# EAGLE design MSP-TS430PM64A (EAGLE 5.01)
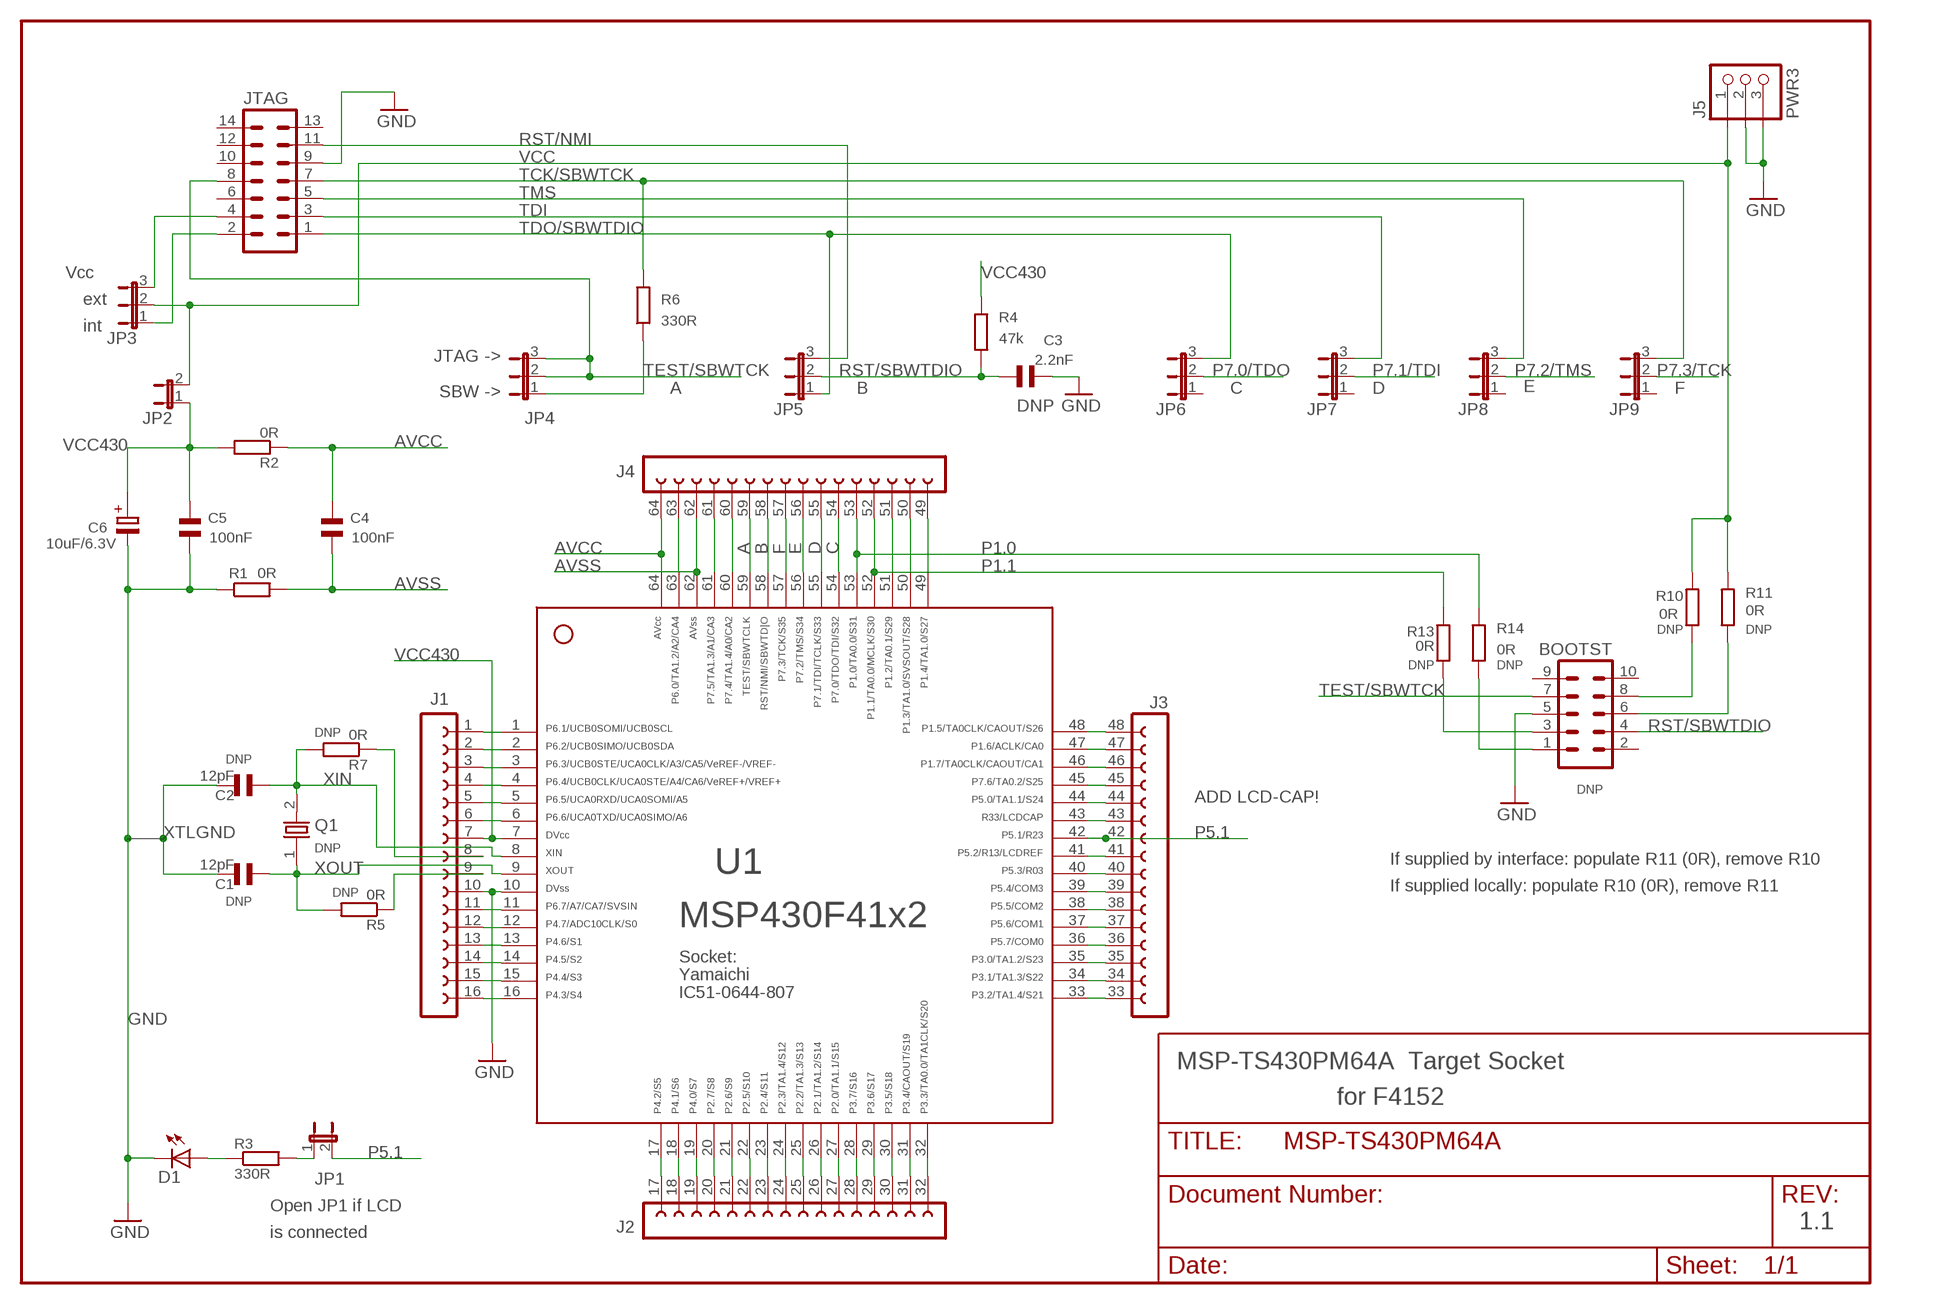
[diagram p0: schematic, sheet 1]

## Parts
BOOTST  ML10  [ML10]
C1  12pF  CSMD0805  [CSMD0805]
C2  12pF  CSMD0805  [CSMD0805]
C3  2.2nF  CSMD0805  [CSMD0805]
C4  100nF  CSMD0805  [CSMD0805]
C5  100nF  CSMD0805  [CSMD0805]
C6  10uF/6.3V  ELKO_1210  [1210ELKO]
D1  LEDCHIPLED_0805  [CHIPLED_0805]
J1  FE16-1-1  [FE16-1-1]
J2  FE16-1-2  [FE16-1-2]
J3  FE16-1-3  [FE16-1-3]
J4  FE16-1-4  [FE16-1-4]
J5  PWR3  [PWR3]
JP1  JP1E  [JP1]
JP2  JP1E  [JP1]
JP3  JP2E  [JP2]
JP4  JP2E  [JP2]
JP5  JP2E  [JP2]
JP6  JP2E  [JP2]
JP7  JP2E  [JP2]
JP8  JP2E  [JP2]
JP9  JP2E  [JP2]
JTAG  ML14  [ML14]
Q1  HCTC_XTLTCV  [TCV]
R1  0R  R_0805  [0805]
R2  0R  R_0805  [0805]
R3  330R  R_0805  [0805]
R4  47k  R_0805  [0805]
R5  0R  R_0805  [0805]
R6  330R  R_0805  [0805]
R7  0R  R_0805  [0805]
R10  0R  R_0805  [0805]
R11  0R  R_0805  [0805]
R13  0R  R_0805  [0805]
R14  0R  R_0805  [0805]
U1  F41X2---PM64QFP64-SOCKET  [IC51-0644-807]

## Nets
A: J4.59 JP4.2 JP4.3 JTAG.8 U1.59
AVCC: C4.1 J4.64 R2.1 U1.64
AVSS: C4.2 J4.62 R1.2 U1.62
B: C3.2 J4.58 JP5.2 R4.2 U1.58
C: J4.54 JP6.2 U1.54
D: J4.55 JP7.2 U1.55
E: J4.56 JP8.2 U1.56
F: J4.57 JP9.2 U1.57
GND: BOOTST.5 C3.1 C5.2 C6.- D1.C J1.10 J5.2 J5.3 JTAG.9 R1.1 U1.10
N$1: J1.9 R5.1
N$2: J1.2 U1.2
N$3: J1.1 U1.1
N$4: J1.4 U1.4
N$5: J1.5 U1.5
N$6: J1.6 U1.6
N$7: JP3.1 JTAG.2
N$8: J2.21 U1.21
N$9: J1.13 U1.13
N$10: J1.8 R7.1
N$11: J1.11 U1.11
N$12: J1.12 U1.12
N$13: J3.33 U1.33
N$14: J1.14 U1.14
N$15: J1.15 U1.15
N$16: J3.34 U1.34
N$18: J3.47 U1.47
N$19: J3.46 U1.46
N$20: J3.45 U1.45
N$21: J3.44 U1.44
N$22: J3.43 U1.43
N$23: JP3.3 JTAG.4
N$24: J3.41 U1.41
N$25: J3.40 U1.40
N$26: J3.39 U1.39
N$27: J3.38 U1.38
N$28: J3.37 U1.37
N$29: J3.36 U1.36
N$30: J3.35 U1.35
N$31: BOOTST.3 R13.1
N$32: J3.48 U1.48
N$33: JP1.1 R3.2
N$34: D1.A R3.1
N$36: J4.61 U1.61
N$37: J4.60 U1.60
N$40: J2.22 U1.22
N$41: BOOTST.1 R14.1
N$42: BOOTST.8 R10.1
N$46: J4.51 U1.51
N$47: J4.50 U1.50
N$48: J4.49 U1.49
N$49: BOOTST.6 R11.1
N$50: J2.18 U1.18
N$51: J2.19 U1.19
N$52: J2.20 U1.20
N$55: J2.23 U1.23
N$56: J2.24 U1.24
N$57: J2.25 U1.25
N$59: J2.27 U1.27
N$61: J2.29 U1.29
N$62: J2.30 U1.30
N$63: J2.31 U1.31
N$64: J2.17 U1.17
N$65: J1.16 U1.16
N$66: J2.28 U1.28
N$67: J2.32 U1.32
N$72: J4.63 U1.63
N$73: J1.3 U1.3
N$74: J2.26 U1.26
N$76: JP4.1 R6.1
P1.0: J4.53 R14.2 U1.53
P1.1: J4.52 R13.2 U1.52
P5.1: J3.42 JP1.2 U1.42
RST/NMI: JP5.3 JTAG.11
RST/SBWTDIO: BOOTST.4
TCK/SBWTCK: JP9.3 JTAG.7 R6.2
TDI: JP7.3 JTAG.3
TDO/SBWTDIO: JP5.1 JP6.3 JTAG.1
TEST/SBWTCK: BOOTST.7
TMS: JP8.3 JTAG.5
VCC: J5.1 JP2.2 JP3.2 R10.2 R11.2
VCC430: C5.1 C6.+ J1.7 JP2.1 R2.2 R4.1 U1.7
XIN: C2.1 Q1.2 R7.2 U1.8
XOUT: C1.1 Q1.1 R5.2 U1.9
XTLGND: C1.2 C2.2
Unconnected: BOOTST.2 BOOTST.9 BOOTST.10 JP6.1 JP7.1 JP8.1 JP9.1 JTAG.6 JTAG.10 JTAG.12 JTAG.13 JTAG.14

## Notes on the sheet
- Vcc
- ext
- int
- JTAG ->
- TEST/SBWTCK | RST/SBWTDIO | P7.0/TDO | P7.1/TDI | P7.2/TMS | P7.3/TCK
- SBW ->
- DNP
- DNP
- DNP
- DNP
- DNP
- DNP
- DNP
- DNP
- ADD LCD-CAP!
- DNP
- If supplied by interface: populate R11 (0R), remove R10
- DNP | If supplied locally: populate R10 (0R), remove R11
- DNP
- Socket:
- Yamaichi
- IC51-0644-807
- MSP-TS430PM64A  Target Socket
- for F4152
- Open JP1 if LCD
- 1.1
- is connected

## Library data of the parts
BOOTST = con-ml:ML10
C1-C5 = cap:CSMD0805
C6 = smd:ELKO_1210
D1 = led:LED: LED
J1 = con-lsta:FE16-1-1
J2 = con-lsta:FE16-1-2
J3 = con-lsta:FE16-1-3
J4 = con-lsta:FE16-1-4
J5 = MSP430:PWR3
JP1 JP2 = jumper:JP1E: JUMPER
JP3-JP9 = jumper:JP2E: JUMPER
JTAG = con-ml:ML14
Q1 = scrystal:HCTC_XTL
R1-R7 R10 R11 R13 R14 = smd:R_0805
U1 = TI_MSP430_v14_intern:F41X2---PM64: ***MSP430F41x2***PM64

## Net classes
0 default: width 0.254 mm, drill 0.559 mm
1 Ground: width 0.203 mm, drill 0.61 mm

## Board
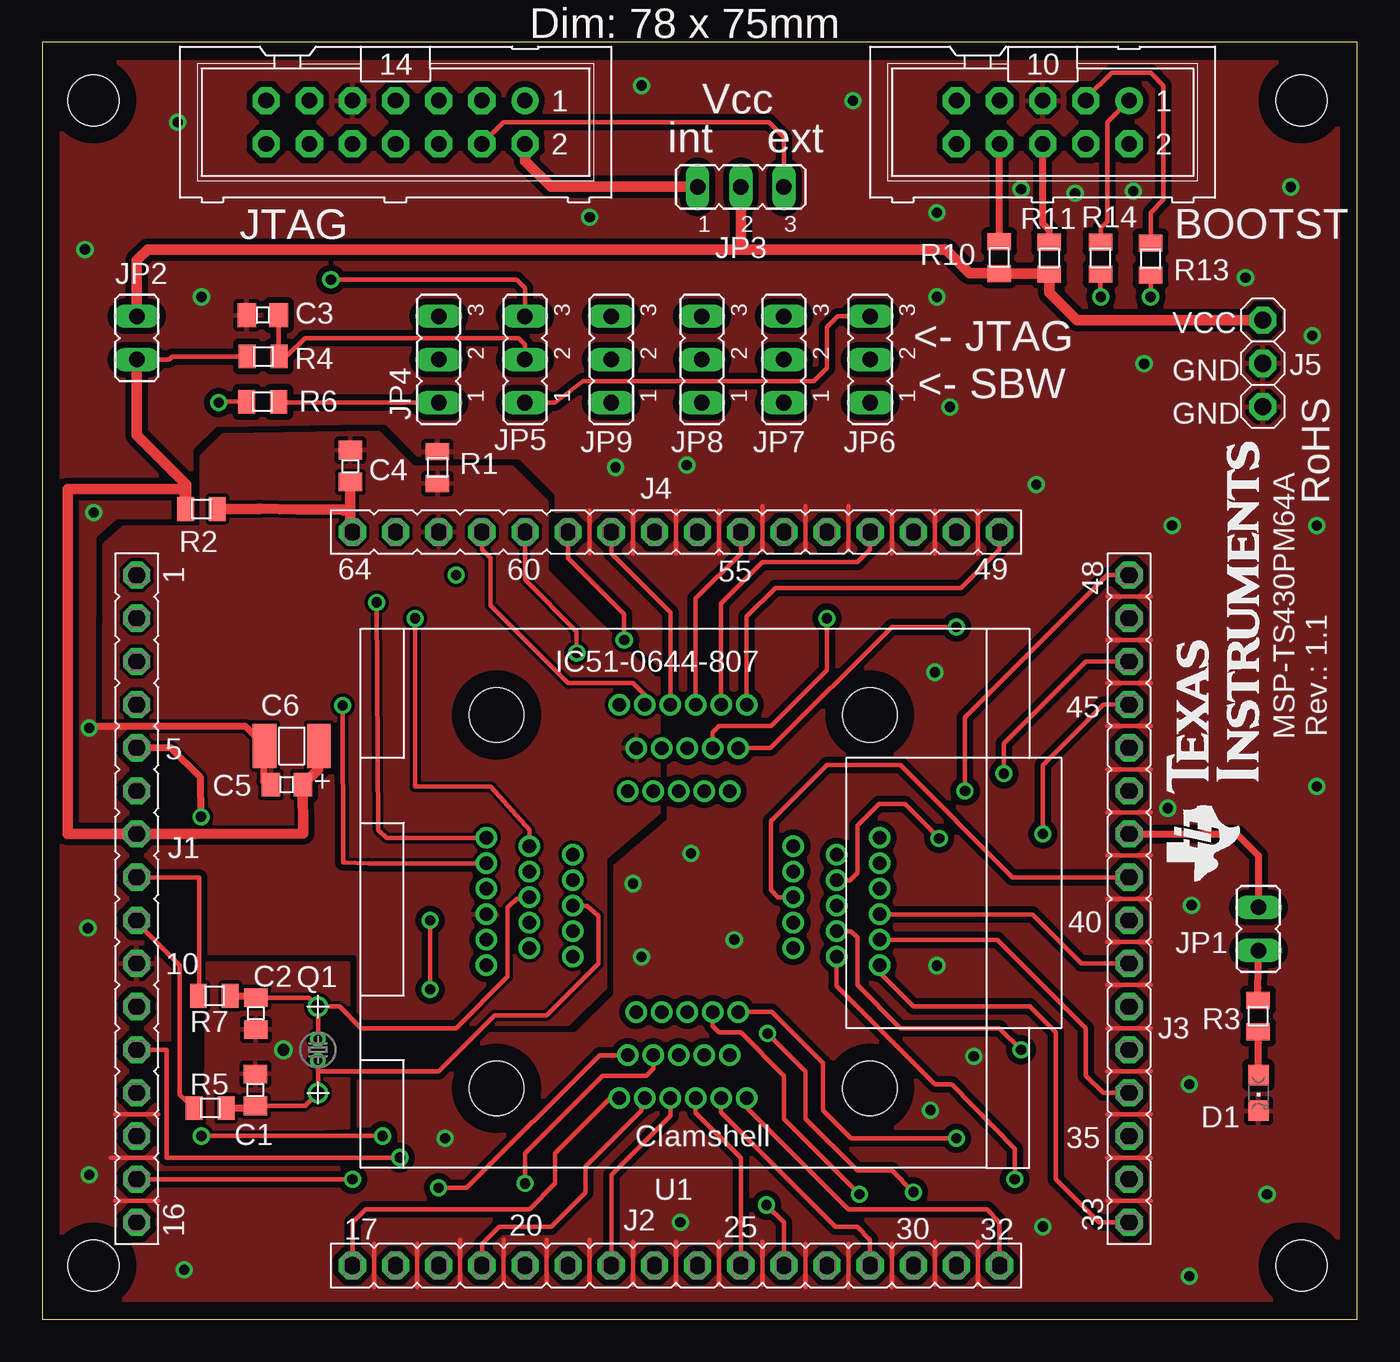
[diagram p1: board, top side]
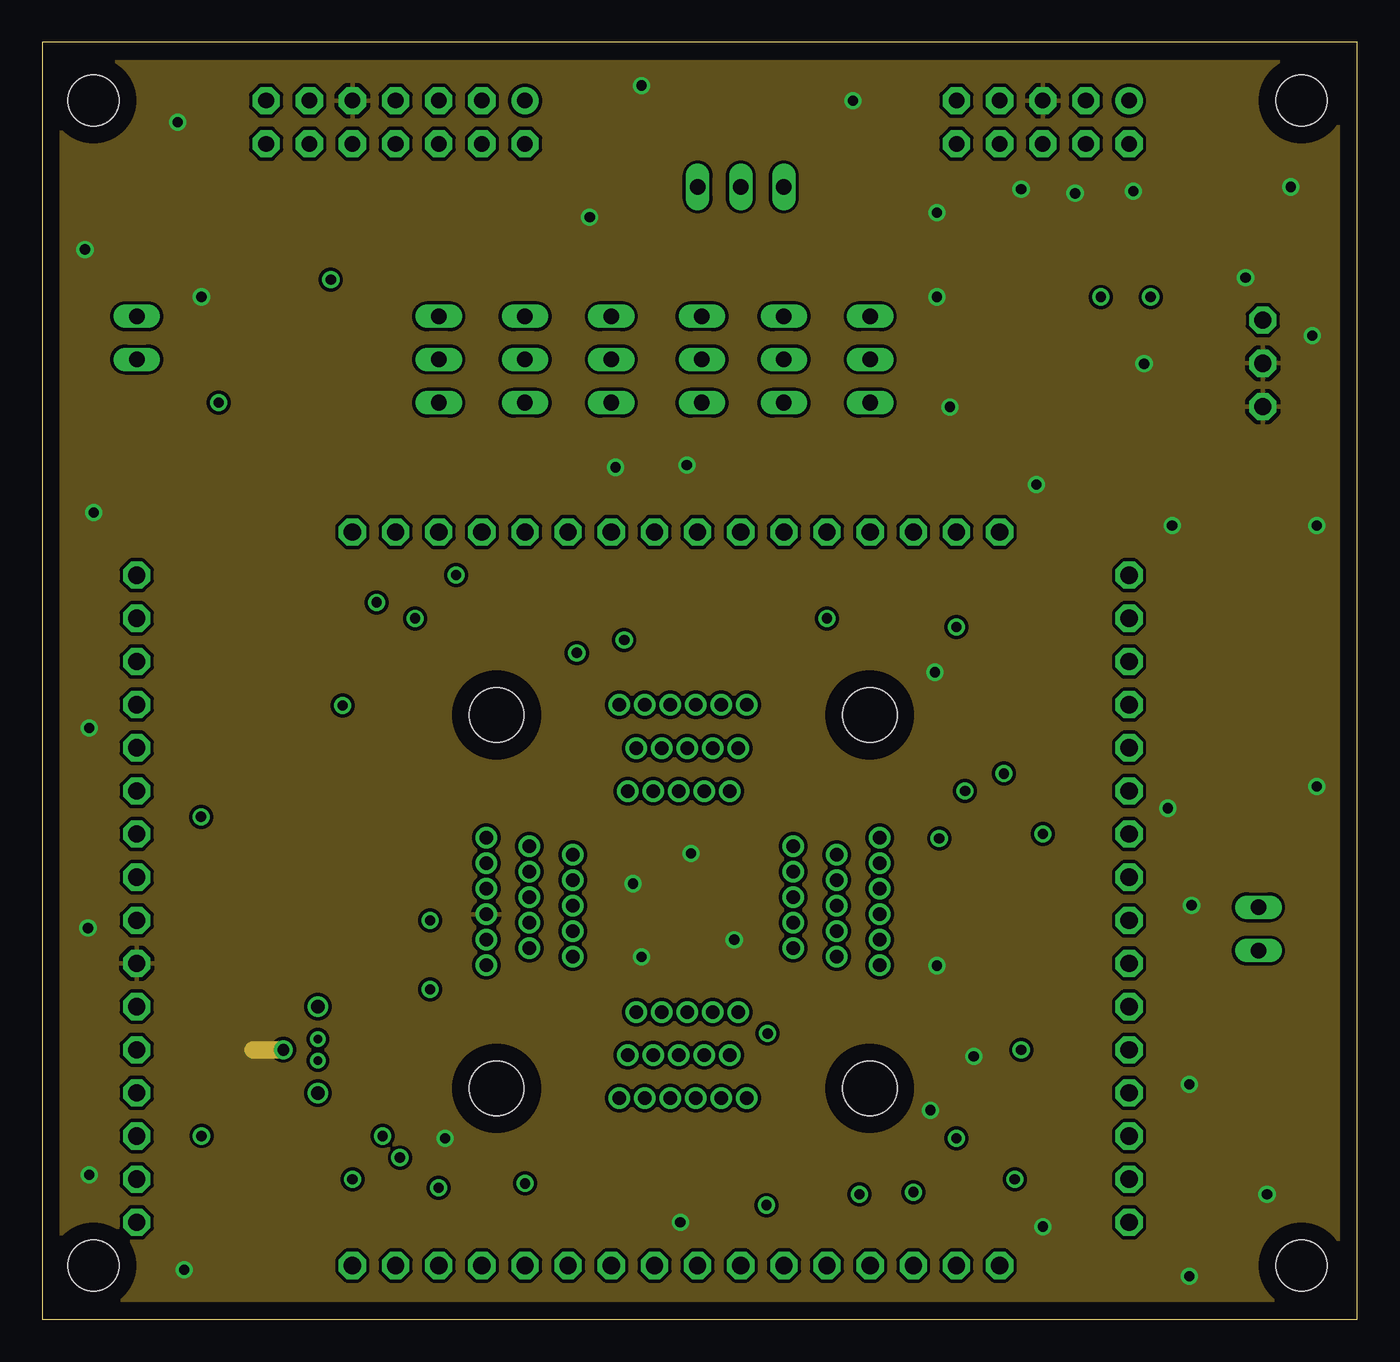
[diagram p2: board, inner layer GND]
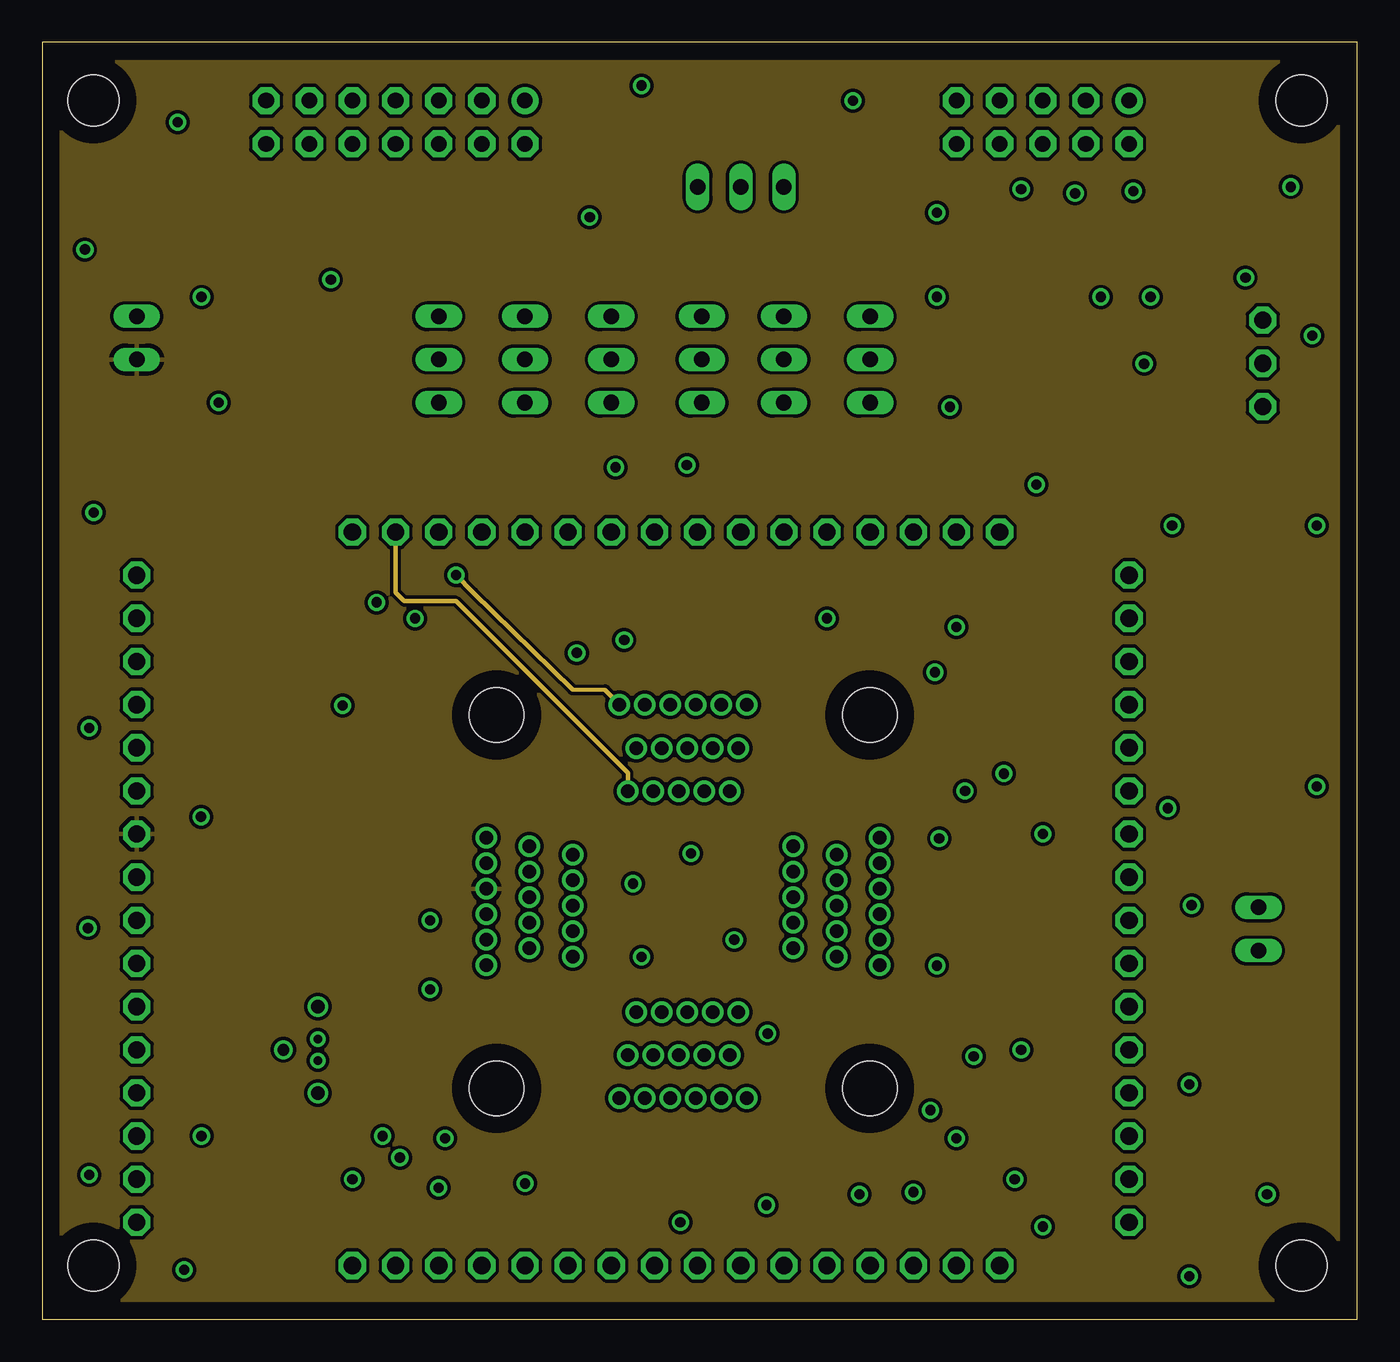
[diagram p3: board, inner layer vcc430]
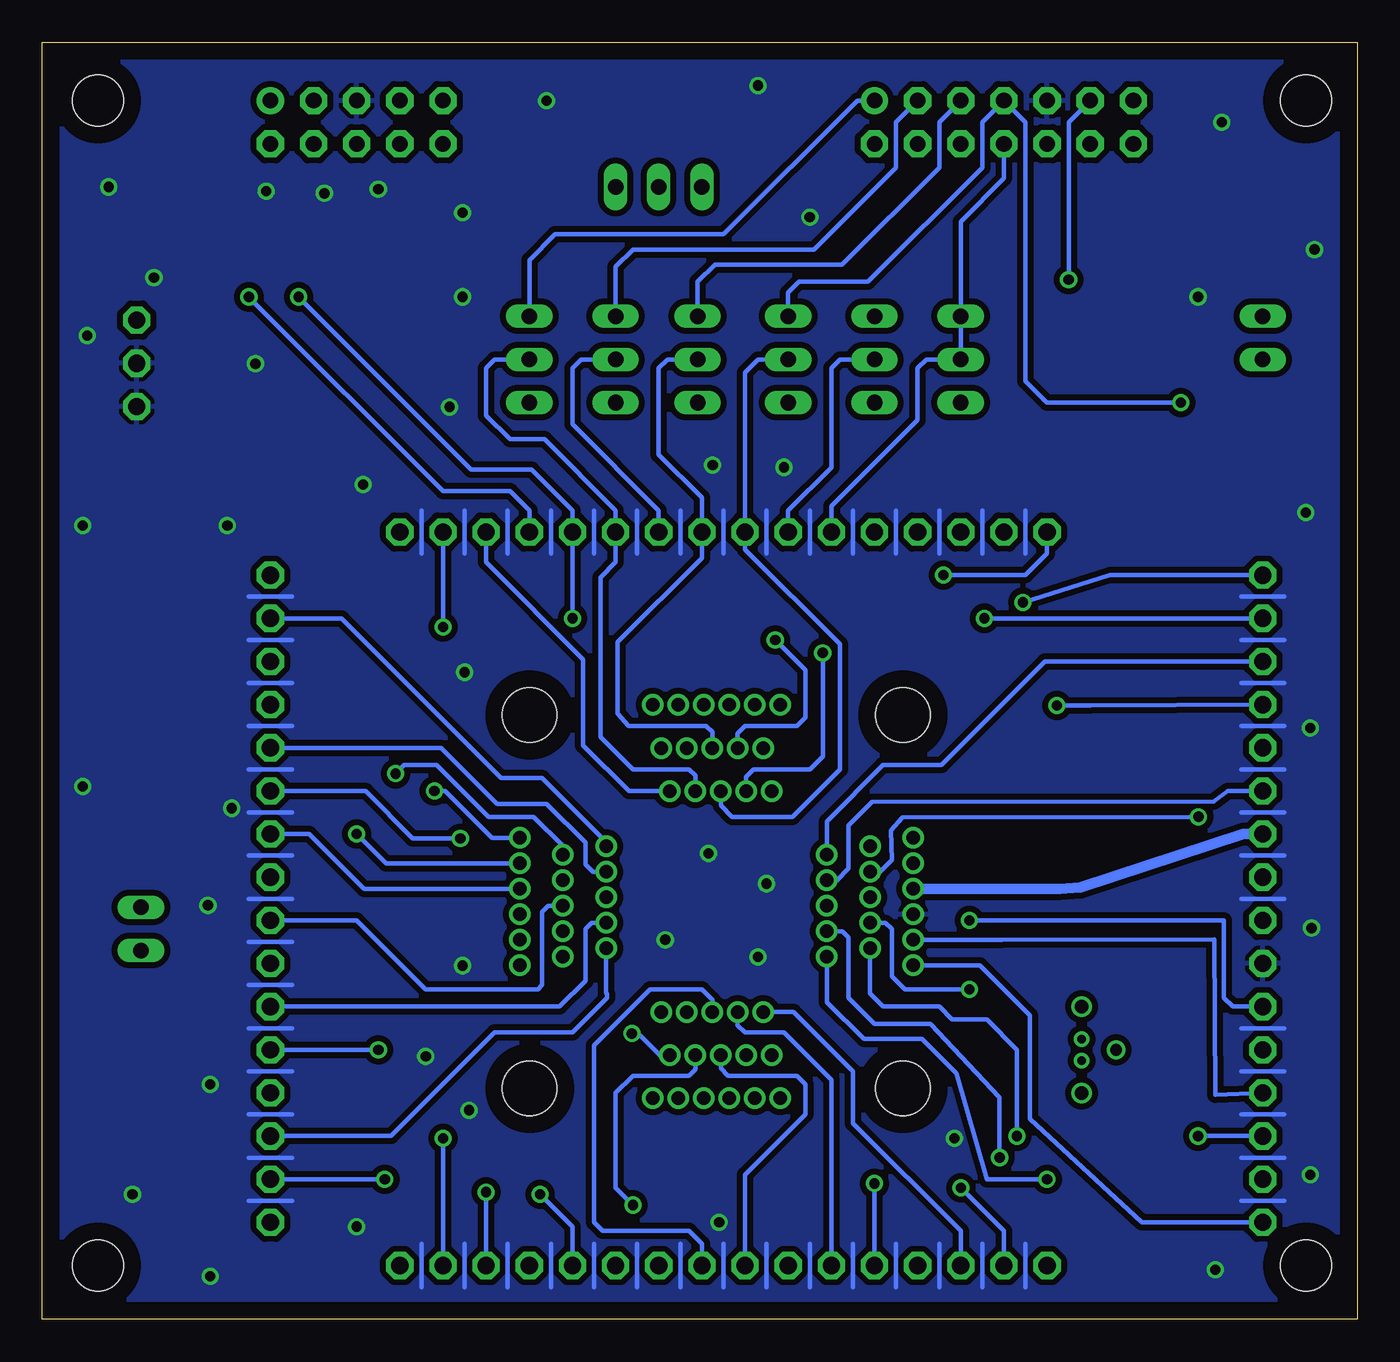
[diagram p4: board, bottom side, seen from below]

Size 77.39 x 75.17 mm. Coordinates in mm from the lower left corner, seen from the top.
Outline: 0,0 77.39,0 77.39,75.17 0,75.17 0,0
Copper layers (1*2*15*16): TOP 0.035mm / dielectric 1.5mm / GND 0.035mm / dielectric 1.5mm / vcc430 0.035mm / dielectric 1.5mm / Bottom 0.035mm
Design rules "default *": minimum track width 10mil, minimum drill 19mil, track to track 8mil, track to pad 8mil, pad to pad 8mil, via to via 8mil, smd to smd 8mil, copper to edge 40mil, drill to drill 8mil, minimum pad ring 8mil, minimum via ring 8mil, stop-mask expansion 0mil, vias tented up to drill 0mil, thermal gap 10mil
Holes 3 mm at 3.01,3.17 3.01,71.75 74.13,3.17 74.13,71.75

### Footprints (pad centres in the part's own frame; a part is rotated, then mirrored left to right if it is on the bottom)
ML10 = drill 0.914 pad 1.6 round: 1 -5.08,-1.27 | drill 0.914 pad 1.6 octagon: 2 -5.08,1.27; 3 -2.54,-1.27; 4 -2.54,1.27; 5 0,-1.27; 6 0,1.27; 7 2.54,-1.27; 8 2.54,1.27; 9 5.08,-1.27; 10 5.08,1.27
CSMD0805 = smd 1.092 x 1.397: 1 -0.94,0; 2 0.94,0
1210ELKO = smd 1.397 x 2.591: + 1.6,0; - -1.6,0
CHIPLED_0805 = smd 1.2 x 1.2: A 0,-1.05; C 0,1.05
FE16-1-1 = drill 1.016 pad 1.6 octagon: 1 -17.78,1.27; 2 -15.24,1.27; 3 -12.7,1.27; 4 -10.16,1.27; 5 -7.62,1.27; 6 -5.08,1.27; 7 -2.54,1.27; 8 0,1.27; 9 2.54,1.27; 10 5.08,1.27; 11 7.62,1.27; 12 10.16,1.27; 13 12.7,1.27; 14 15.24,1.27; 15 17.78,1.27; 16 20.32,1.27
FE16-1-2 = drill 1.016 pad 1.6 octagon: 17 -17.78,1.27; 18 -15.24,1.27; 19 -12.7,1.27; 20 -10.16,1.27; 21 -7.62,1.27; 22 -5.08,1.27; 23 -2.54,1.27; 24 0,1.27; 25 2.54,1.27; 26 5.08,1.27; 27 7.62,1.27; 28 10.16,1.27; 29 12.7,1.27; 30 15.24,1.27; 31 17.78,1.27; 32 20.32,1.27
FE16-1-3 = drill 1.016 pad 1.6 octagon: 33 -17.78,1.27; 34 -15.24,1.27; 35 -12.7,1.27; 36 -10.16,1.27; 37 -7.62,1.27; 38 -5.08,1.27; 39 -2.54,1.27; 40 0,1.27; 41 2.54,1.27; 42 5.08,1.27; 43 7.62,1.27; 44 10.16,1.27; 45 12.7,1.27; 46 15.24,1.27; 47 17.78,1.27; 48 20.32,1.27
FE16-1-4 = drill 1.016 pad 1.6 octagon: 49 -17.78,1.27; 50 -15.24,1.27; 51 -12.7,1.27; 52 -10.16,1.27; 53 -7.62,1.27; 54 -5.08,1.27; 55 -2.54,1.27; 56 0,1.27; 57 2.54,1.27; 58 5.08,1.27; 59 7.62,1.27; 60 10.16,1.27; 61 12.7,1.27; 62 15.24,1.27; 63 17.78,1.27; 64 20.32,1.27
PWR3 = drill 1.016 pad 1.6 octagon: 1 -2.54,0; 2 0,0; 3 2.54,0
JP1 = drill 0.914 long: 1 0,-1.27; 2 0,1.27
JP2 = drill 0.914 long: 1 -2.54,0; 2 0,0; 3 2.54,0
ML14 = drill 0.914 pad 1.6 round: 1 -7.62,-1.27 | drill 0.914 pad 1.6 octagon: 2 -7.62,1.27; 3 -5.08,-1.27; 4 -5.08,1.27; 5 -2.54,-1.27; 6 -2.54,1.27; 7 0,-1.27; 8 0,1.27; 9 2.54,-1.27; 10 2.54,1.27; 11 5.08,-1.27; 12 5.08,1.27; 13 7.62,-1.27; 14 7.62,1.27
TCV = drill 0.5 round: 1 -0.635,0; 2 0.635,0
0805 = smd 1 x 1.4: 1 -0.94,0; 2 0.94,0
IC51-0644-807 = drill 0.8 pad 1.27 round: 1 11.652,-4.194; 2 9.112,-3.694; 3 6.572,-3.194; 4 11.652,-2.694; 5 9.112,-2.194; 6 6.572,-1.694; 7 11.652,-1.194; 8 9.112,-0.694; 9 6.572,-0.194; 10 11.652,0.306; 11 9.112,0.806; 12 6.572,1.306; 13 11.652,1.806; 14 9.112,2.306; 15 6.572,2.806; 16 11.652,3.306; 17 3.822,11.136; 18 3.322,8.596; 19 2.822,6.056; 20 2.322,11.136; 21 1.822,8.596; 22 1.322,6.056; 23 0.822,11.136; 24 0.322,8.596; 25 -0.178,6.056; 26 -0.678,11.136; 27 -1.178,8.596; 28 -1.678,6.056; 29 -2.178,11.136; 30 -2.678,8.596; 31 -3.178,6.056; 32 -3.678,11.136; 33 -11.508,3.306; 34 -8.968,2.806; 35 -6.428,2.306; 36 -11.508,1.806; 37 -8.968,1.306; 38 -6.428,0.806; 39 -11.508,0.306; 40 -8.968,-0.194; 41 -6.428,-0.694; 42 -11.508,-1.194; 43 -8.968,-1.694; 44 -6.428,-2.194; 45 -11.508,-2.694; 46 -8.968,-3.194; 47 -6.428,-3.694; 48 -11.508,-4.194; 49 -3.678,-12.024; 50 -3.178,-9.484; 51 -2.678,-6.944; 52 -2.178,-12.024; 53 -1.678,-9.484; 54 -1.178,-6.944; 55 -0.678,-12.024; 56 -0.178,-9.484; 57 0.322,-6.944; 58 0.822,-12.024; 59 1.322,-9.484; 60 1.822,-6.944; 61 2.322,-12.024; 62 2.822,-9.484; 63 3.322,-6.944; 64 3.822,-12.024 | hole 3.2: -10.922,10.541; 11.049,10.541; 11.049,-11.43; -10.922,-11.43

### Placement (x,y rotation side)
BOOTST  58.89,70.48 180 top
C1  12.54,13.51 90 top
C2  12.56,18 270 top
C3  12.97,59.13 0 top
C4  18.12,50.24 90 top
C5  14.39,31.48 180 top
C6  14.68,33.76 0 top
D1  71.59,13.33 180 top
J1  4.28,26.03 270 top
J2  36.03,1.9 0 top
J3  65.24,23.49 90 top
J4  38.57,47.62 180 top
J5  71.84,56.28 270 top
JP1  71.59,22.98 0 top
JP2  5.55,57.78 0 top
JP3  41.11,66.67 0 top
JP4  23.33,56.51 90 top
JP5  28.41,56.51 90 top
JP6  48.73,56.51 90 top
JP7  43.65,56.51 90 top
JP8  38.82,56.51 90 top
JP9  33.49,56.51 90 top
JTAG  20.79,70.48 180 top
Q1  16.22,15.87 90 top
R1  23.25,50.13 270 top
R2  9.36,47.71 180 top
R3  71.56,17.85 90 top
R4  12.99,56.69 0 top
R5  9.87,12.44 0 top
R6  12.97,54.02 180 top
R7  10.12,19.05 0 top
R10  56.32,62.5 270 top
R11  59.27,62.48 270 top
R13  65.24,62.43 270 top
R14  62.29,62.48 270 top
U1  37.78,24.15 180 top
U$1  [LOGO2008_TPLACE]  69.3,35.81 90 top

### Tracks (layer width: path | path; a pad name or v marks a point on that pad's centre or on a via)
A  (via drill 0.6)
  TOP 0.254: v34.25,40 34.25,41.52 30.95,44.83 J4.59
  Bottom 0.254: U1.59 36.46,34.49 36.03,34.92 32.98,34.92 32.47,35.43 32.47,38.22 v34.25,40 | J4.59 30.95,47.87 25.87,52.95 25.87,56 25.36,56.51 JP4.2 JP4.3 23.33,64.64 20.79,67.18 JTAG.8
AVCC  (via drill 0.6)
  TOP 0.61: J4.64 18.25,46.6 18.12,46.73 18.12,47.62 | 18.12,47.62 C4.1 | 18.12,47.62 18,47.62 17.95,47.67 17.79,47.67 17.74,47.62 17.69,47.67 15.02,47.67 12.79,47.75 12.75,47.71 R2.1
  vcc430 0.254: U1.64 33.12,37.06 31.2,37.08 25.36,42.79 v24.35,43.81
  Bottom 0.254: v24.35,43.81 19.52,43.81 18.25,45.08 J4.64
AVSS
  pour TOP (rank 2): 27.65,50.16 29.68,48.13 29.68,44.06 36.03,37.71 36.28,37.71 36.28,29.84 33.11,27.17 33.11,19.55 30.95,17.39 19.09,17.37 19.09,21.53 9.31,21.53 9.31,17.14 4.33,17.14 3.57,17.9 3.67,45.61 4.79,46.6 9.39,46.6 9.39,50.79 10.66,52.06 19.77,52.19 21.81,50.16
B
  TOP 0.254: U1.58 36.96,41.61 33.49,45.08 J4.58 | JP5.2 28.41,57.4 28.03,57.78 15.46,57.78 14.44,56.76 14.06,56.76 13.98,56.69 R4.2 13.93,56.76 13.91,56.79 C3.2
  Bottom 0.254: JP5.2 30.44,56.51 30.95,56 30.95,50.16 33.49,47.62 J4.58
C
  Bottom 0.254: U1.54 38.96,32.01 39.33,32.38 42.63,32.38 44.54,34.28 44.54,43.68 43.65,44.57 J4.54 43.65,47.62 47.84,51.81 49.87,51.81 51.27,53.21 51.27,56 50.76,56.51 JP6.2
D
  TOP 0.254: U1.55 38.46,42.43 41.11,45.08 J4.55
  Bottom 0.254: JP7.2 45.68,56.51 46.19,56 46.19,52.7 41.11,47.62 J4.55
E
  Bottom 0.254: U1.56 37.96,34.56 38.32,34.92 42.89,34.92 43.52,35.68 43.52,39.87 38.57,44.83 J4.56 38.57,48.38 41.11,50.92 41.11,56 40.6,56.51 JP8.2
F
  Bottom 0.254: U1.57 37.46,30.25 36.79,29.59 33.24,29.59 30.44,32.38 30.44,39.75 36.03,45.33 J4.57 36.03,55.75 35.27,56.51 JP9.2
GND  (via drill 0.6)
  TOP 0.254: 4.03,9.52 6.57,9.52 | 4.28,12.06 6.82,12.06 | 4.28,6.98 6.82,6.98 | 19.52,1.9 19.52,4.44 | 22.06,1.9 22.06,4.44 | 24.6,2.15 24.6,4.69 | 27.14,2.15 27.14,4.69 | 29.68,2.15 29.68,4.69 | 32.22,2.15 32.22,4.69 | 34.76,2.03 34.76,4.57 | 37.3,2.03 37.3,4.57 | 39.84,2.03 39.84,4.57 | 42.38,2.03 42.38,4.57 | 44.92,1.9 44.92,4.44 | 47.46,1.9 47.46,4.44 | 50,1.9 50,4.44 | 52.54,2.03 52.54,4.57 | 55.08,2.03 55.08,4.57 | 62.7,6.98 65.24,6.98 | 62.7,9.52 65.24,9.52 | 62.7,12.06 65.24,12.06 | 62.7,14.6 65.24,14.6 | 62.7,17.14 65.24,17.14 | 62.7,19.68 65.24,19.68 | 62.7,22.22 65.24,22.22 | 62.7,24.76 65.24,24.76 | 62.7,27.3 65.24,27.3 | 62.7,29.84 65.24,29.84 | 62.7,32.38 65.24,32.38 | 62.7,34.92 65.24,34.92 | 62.7,37.46 65.24,37.46 | 62.7,40 65.24,40 | 62.7,42.54 65.24,42.54 | 55.08,45.08 55.08,47.62 | 52.54,45.08 52.54,47.62 | 50,45.08 50,47.62 | 47.46,45.33 47.46,47.87 | 44.92,45.33 44.92,47.87 | 42.38,45.33 42.38,47.87 | 39.84,45.08 39.84,47.62 | 37.3,45.08 37.3,47.62 | 34.76,45.08 34.76,47.62 | 32.22,45.08 32.22,47.62
  TOP 0.406: C5.2 13.02,31.68 13.02,33.78 13.07,33.78 C6.- 11.92,34.92 3.11,34.92 v2.76,34.82
  GND 1.016: 12.41,15.87 14.19,15.87
  Bottom 0.254: 4.28,37.46 6.82,37.46 | 4.28,40 6.82,40 | 4.28,42.54 6.82,42.54 | 4.28,34.92 6.82,34.92 | 4.28,32.38 6.82,32.38 | 4.28,29.84 6.82,29.84 | 4.28,27.3 6.82,27.3 | 4.28,24.76 6.82,24.76 | 4.28,17.14 6.82,17.14 | 4.28,14.6 6.82,14.6 | 4.28,12.06 6.82,12.06 | 4.28,9.52 6.82,9.52 | 4.28,6.98 6.82,6.98 | 19.52,1.9 19.52,4.44 | 22.06,1.9 22.06,4.44 | 24.6,1.9 24.6,4.44 | 27.14,1.9 27.14,4.44 | 29.68,1.9 29.68,4.44 | 32.22,1.9 32.22,4.44 | 34.76,1.9 34.76,4.44 | 37.3,1.9 37.3,4.44 | 39.84,1.9 39.84,4.44 | 42.38,1.9 42.38,4.44 | 44.92,1.9 44.92,4.44 | 47.46,1.9 47.46,4.44 | 50,1.9 50,4.44 | 52.54,1.9 52.54,4.44 | 55.08,1.9 55.08,4.44 | 62.7,6.98 65.24,6.98 | 62.7,9.52 65.24,9.52 | 62.7,12.06 65.24,12.06 | 62.7,14.6 65.24,14.6 | 62.7,17.14 65.24,17.14 | 62.7,19.68 65.24,19.68 | 62.7,22.22 65.24,22.22 | 62.7,24.76 65.24,24.76 | 62.7,27.3 65.24,27.3 | 62.7,29.84 65.24,29.84 | 62.7,32.38 65.24,32.38 | 62.7,34.92 65.24,34.92 | 62.7,37.46 65.24,37.46 | 62.7,40 65.24,40 | 62.7,42.54 65.24,42.54 | 55.08,45.08 55.08,47.62 | 52.54,45.08 52.54,47.62 | 50,45.08 50,47.62 | 47.46,45.08 47.46,47.62 | 42.38,45.08 42.38,47.62 | 39.84,45.08 39.84,47.62 | 37.3,45.08 37.3,47.62 | 34.76,45.08 34.76,47.62 | 32.22,45.08 32.22,47.62 | 29.68,45.08 29.68,47.62 | 27.14,45.08 27.14,47.62 | 24.6,45.08 24.6,47.62 | 22.06,45.08 22.06,47.62 | 19.52,45.08 19.52,47.62 | 44.92,45.08 44.92,47.62
  other vias: 38.19,27.43 34.76,25.65 35.27,21.33 40.73,22.35 60.79,66.29 57.62,66.54 64.22,66.42 73.5,66.67 70.83,61.34 74.77,57.91 75.02,46.73 75.02,31.36 66.26,30.09 67.65,24.38 67.53,13.84 72.1,7.36 67.53,2.54 58.89,5.46 54.83,15.49 52.67,20.82 52.29,12.31 37.55,5.71 23.71,10.66 8.34,2.92 2.76,8.5 2.68,23.03 3.01,47.49 2.5,62.99 7.96,70.48 9.36,60.19 52.67,60.19 53.43,53.72 35.27,72.64 47.71,71.75 52.67,65.15 64.86,56.26 58.51,49.14 52.54,38.09 66.51,46.73 37.93,50.29 33.74,50.16 32.22,64.89
  pour TOP (isolate 0.356, rank 3): 0.41,0.38 76.89,0.38 76.92,49.14 76.92,74.48 0.41,74.48
  pour Bottom (isolate 0.356): 0.47,0.38 76.91,0.35 76.91,74.58 3.64,74.48 0.47,74.48
  pour GND (rank 2): 0.47,0.63 76.67,0.63 76.67,74.29 0.47,74.29
N$1
  TOP 0.254: R5.1 8.09,13.2 8.09,20.82 5.55,23.36 J1.9
N$2  (via drill 0.6)
  TOP 0.254: U1.2 28.67,28.82 26.38,31.36 21.93,31.36 v21.93,41.27
  Bottom 0.254: J1.2 v21.93,41.27
N$3  (via drill 0.6)
  TOP 0.254: U1.1 20.25,28.34 19.77,28.82 v19.67,42.21
  Bottom 0.254: v19.67,42.21 14.57,43.81 J1.1
N$4  (via drill 0.6)
  TOP 0.254: U1.4 19.21,26.84 17.69,26.89 v17.67,36.14
  Bottom 0.254: v17.67,36.14 15.71,36.14 J1.4
N$5  (via drill 0.6)
  TOP 0.406: J1.5 7.56,33.65 9.31,31.9 v9.34,29.59
  Bottom 0.254: U1.5 28.1,26.34 27.39,27.05 27.45,28.77 26.76,29.54 v9.34,29.59
N$6
  Bottom 0.254: U1.6 30.63,25.84 29.93,26.54 29.93,29.08 28.56,30.45 8.45,30.47 7.61,31.11 J1.6
N$7
  TOP 0.61: JTAG.2 28.41,68.19 29.93,66.67 JP3.1
N$8  (via drill 0.6)
  TOP 0.254: U1.21 35.96,14.79 35.52,14.35 32.98,14.35 28.66,10.03 28.41,9.77 v28.41,8
  Bottom 0.254: J2.21 v28.41,8
N$9
  Bottom 0.254: U1.13 20.91,22.34 8.39,22.37 8.34,13.2 J1.13
N$10
  TOP 0.254: 9.23,19.05 9.23,26.03 J1.8
  TOP 0.406: R7.1 9.23,19.05
N$11  (via drill 0.6)
  TOP 0.254: v22.82,23.49 v22.82,19.43
  Bottom 0.254: U1.11 27.76,23.34 27.39,22.98 27.39,20.19 26.63,19.43 v22.82,19.43 | v22.82,23.49 7.84,23.49 7.84,18.92 7.33,18.41 J1.11
N$12  (via drill 0.6)
  TOP 0.254: J1.12 7.33,15.87 7.33,9.52 v21.04,9.52
  Bottom 0.254: U1.12 30.3,22.84 29.93,22.47 29.93,18.92 28.41,17.39 25.11,17.39 21.04,13.08 v21.04,9.52
N$13
  TOP 0.254: U1.33 49.29,20.39 51.27,18.41 58.13,18.41 59.65,16.89 59.65,8.25 62.19,5.71 J3.33
N$14  (via drill 0.6)
  TOP 0.254: v9.36,10.79 v20.03,10.79
  Bottom 0.254: U1.14 28.67,19.18 27.9,18.41 24.6,18.41 23.84,17.65 21.81,17.65 20.03,15.87 v20.03,10.79 | J1.14 v9.36,10.79
N$15  (via drill 0.6)
  TOP 0.254: J1.15 v18.25,8.25
  Bottom 0.254: U1.15 31.21,18.67 29.05,16.5 25.62,16.5 23.58,14.47 21.81,8.25 v18.25,8.25
N$16  (via drill 0.6)
  TOP 0.254: U1.34 46.75,19.63 52.54,13.84 53.56,13.84 57.24,10.03 v57.24,8.25
  Bottom 0.254: v57.24,8.25 J3.34
N$18
  Bottom 0.254: U1.47 44.21,28.11 47.97,31.87 50.38,31.87 59.78,41.27 J3.47
N$19  (via drill 0.6)
  TOP 0.254: v56.6,32.13 56.6,33.9 61.43,38.73 J3.46
  Bottom 0.254: U1.46 46.75,27.86 48.48,29.59 51.14,29.59 54.19,32.63 56.1,32.63 v56.6,32.13
N$20  (via drill 0.6)
  TOP 0.254: v58.89,28.57 58.89,32.63 62.45,36.19 J3.45
  Bottom 0.254: U1.45 57.16,26.84 v58.89,28.57
N$21
  Bottom 0.254: U1.44 44.98,26.34 45.43,26.79 45.43,28.06 47.71,30.35 50.63,30.35 53.94,33.65 J3.44
N$22  (via drill 0.6)
  TOP 0.254: U1.43 47.53,25.84 47.97,26.28 47.97,29.08 49.24,30.35 50.76,30.35 v52.79,28.32
  Bottom 0.254: v52.79,28.32 55.59,28.32 58.38,31.11 J3.43
N$23
  TOP 0.254: JP3.3 43.65,69.59 42.76,70.48 27.14,70.48 JTAG.4
N$24
  TOP 0.254: U1.41 43.31,24.84 42.89,25.27 42.89,29.33 46.19,32.63 50.51,32.63 57.11,26.03 J3.41
N$25
  Bottom 0.254: U1.40 47.62,24.34 47.97,24 47.97,19.68 48.22,19.43 54.83,19.43 58.89,23.49 J3.40
N$26
  TOP 0.254: U1.39 58.28,23.84 61.18,20.95 J3.39
N$27
  Bottom 0.254: U1.38 45.07,23.34 45.43,22.98 45.43,19.93 46.95,18.41 J3.38
N$28  (via drill 0.6)
  TOP 0.254: U1.37 47.6,22.84 47.97,22.47 47.97,19.68 50.51,17.14 56.35,17.14 v57.62,15.87
  Bottom 0.254: v57.62,15.87 J3.37
N$29
  TOP 0.254: U1.36 56.23,22.34 61.43,17.14 61.43,14.35 62.45,13.33 J3.36
N$30
  Bottom 0.254: U1.35 44.21,19.23 44.16,19.17 44.16,18.92 46.19,16.89 50.76,16.89 56.86,10.79 J3.35
N$31
  TOP 0.254: BOOTST.3 61.43,71.88 62.95,73.4 65.24,73.4 66,72.64 66,65.91 65.24,65.15 R13.1
N$32  (via drill 0.6)
  TOP 0.254: v54.32,31.11 54.32,35.43 62.7,43.81 J3.48
  Bottom 0.254: U1.48 50.92,28.34 53.68,31.11 v54.32,31.11
N$33
  TOP 0.406: R3.2 71.57,19.53 71.59,20.44 JP1.1
N$34
  TOP 0.406: D1.A 71.59,16.25 71.57,16.53 R3.1
N$36
  TOP 0.254: U1.61 35.46,36.76 34.76,37.46 30.95,37.46 26.38,42.03 26.38,44.83 25.87,45.33 J4.61
N$37  (via drill 0.6)
  TOP 0.254: v31.46,39.24 31.46,40.51 28.41,43.56 J4.60
  Bottom 0.254: U1.60 35.96,31.94 35.52,32.38 32.22,32.38 31.46,33.14 v31.46,39.24
N$40
  Bottom 0.254: U1.22 36.46,17.32 36.03,16.89 33.74,16.89 30.95,14.09 J2.22
N$41
  TOP 0.254: BOOTST.1 62.7,70.48 62.7,64.64 62.32,64.26 62.32,63.62 62.29,63.6 R14.1
N$42
  TOP 0.406: R10.1 56.32,63.6 56.35,63.62 BOOTST.8
N$46
  Bottom 0.254: U1.51 42.87,31.09 45.55,33.78 45.55,38.86 51.27,44.57 J4.51
N$47  (via drill 0.6)
  TOP 0.254: U1.50 42.87,33.63 50,40.76 v53.81,40.76
  Bottom 0.254: v53.81,40.76 J4.50
N$48
  TOP 0.254: U1.49 41.46,41.37 43.14,43.05 54.06,43.05 56.35,45.33 J4.49
N$49
  TOP 0.406: BOOTST.6 58.89,64.51 59.27,64.13 R11.1
N$50  (via drill 0.6)
  TOP 0.254: U1.18 32.79,15.55 24.98,7.74 v23.33,7.74
  Bottom 0.254: v23.33,7.74 20.79,5.2 J2.18
N$51
  Bottom 0.254: U1.19 33.17,18.09 29.68,14.6 29.68,11.55 23.33,5.2 J2.19
N$52
  TOP 0.254: U1.20 35.27,12.82 35.27,12.31 31.97,9.01 31.97,7.49 29.93,5.46 26.89,5.46 25.87,4.44 J2.20
N$55
  TOP 0.254: U1.23 36.96,11.98 33.49,8.5 J2.23
N$56
  Bottom 0.254: U1.24 37.46,14.76 37.05,14.35 32.98,14.35 32.47,13.84 32.47,12.06 36.03,8.5 J2.24
N$57
  Bottom 0.254: U1.25 37.96,18.82 38.57,19.43 41.62,19.43 44.92,16.12 44.92,5.71 44.41,5.2 43.4,5.2 39.33,5.2 38.57,4.44 J2.25
N$59  (via drill 0.6)
  TOP 0.254: v42.63,6.73 43.65,5.71 J2.27
  Bottom 0.254: U1.27 38.96,14.72 39.33,14.35 42.63,14.35 43.65,13.33 43.65,8.25 43.65,7.74 v42.63,6.73
N$61
  TOP 0.254: U1.29 39.96,12.19 46.7,5.46 47.97,5.46 48.73,4.69 J2.29
N$62  (via drill 0.6)
  TOP 0.254: 42.63,16.89 v42.7,16.82 44.92,14.6 44.92,11.81 47.97,8.76 50,8.76 v51.27,7.49
  Bottom 0.254: U1.30 41.05,15.55 42.38,16.89 v42.7,16.82 | v51.27,7.49 J2.30
N$63  (via drill 0.6)
  TOP 0.254: U1.31 42.95,18.09 45.94,15.11 45.94,12.31 47.59,10.66 v53.81,10.66
  Bottom 0.254: v53.81,10.66 J2.31
N$64
  TOP 0.254: U1.17 33.43,13.01 30.19,9.77 30.19,8 28.66,6.47 19.01,6.47 18.25,5.71 J2.17
N$65
  Bottom 0.254: U1.16 22.21,20.84 19.27,17.9 19.27,11.81 12.66,5.71 J1.16
N$66  (via drill 0.6)
  TOP 0.254: U1.28 39.46,17.27 39.84,16.89 41.11,16.89 43.65,14.35 43.65,11.81 v48.09,7.36
  Bottom 0.254: J2.28 46.19,5.33 | 46.19,5.33 46.19,5.2 | 46.19,5.33 46.19,5.46 v48.09,7.36
N$67
  TOP 0.254: U1.32 41.46,12.47 47.46,6.47 55.59,6.47 56.35,5.71 J2.32
N$72
  vcc430 0.254: J4.63 20.79,42.79 21.3,42.29 24.35,42.29 34.46,32.17 U1.63
N$73
  Bottom 0.254: U1.3 31.21,29.32 27.9,32.63 24.47,32.63 18.38,38.73 J1.3
N$74
  TOP 0.254: U1.26 38.46,12.17 41.11,9.52 J2.26
N$76
  TOP 0.254: R6.1 13.96,53.97 JP4.1
P1.0  (via drill 0.6)
  TOP 0.254: U1.53 39.46,34.54 39.84,34.92 42.89,34.92 46.19,38.22 v46.19,41.27 | R14.2 62.29,60.22 v62.32,60.19
  Bottom 0.254: v46.19,41.27 J4.53 46.19,47.62 48.6,50.03 52.16,50.03 v62.32,60.19
P1.1  (via drill 0.6)
  TOP 0.254: U1.52 39.96,42.15 42.38,44.57 47.97,44.57 48.73,45.33 J4.52 | v65.24,60.19 R13.2
  Bottom 0.254: v65.24,60.19 53.81,48.76 49.87,48.76 48.73,47.62 J4.52
P5.1
  TOP 0.406: J3.42 70.32,28.57 71.59,27.3 JP1.2
  Bottom 0.254: U1.42 58.46,25.34 61.68,28.57 J3.42
RST/NMI  (via drill 0.6)
  TOP 0.254: v16.98,61.21 27.9,61.21 28.41,60.7 JP5.3
  Bottom 0.254: JTAG.11 16.98,70.48 v16.98,61.21
TCK/SBWTCK  (via drill 0.6)
  TOP 0.254: R6.2 10.43,54.02 v10.38,53.97
  Bottom 0.254: JP9.3 33.49,60.45 32.85,61.08 28.79,61.08 22.06,67.81 22.06,70.48 JTAG.7 19.52,70.48 19.52,55.24 18.25,53.97 v10.38,53.97
TDI
  Bottom 0.254: JTAG.3 27.14,70.48 27.14,67.81 31.97,62.99 42.63,62.99 43.65,61.97 JP7.3
TDO/SBWTDIO
  TOP 0.254: JP5.1 30.19,53.97 31.84,55.24 45.43,55.24 46.19,56 46.19,58.41 46.82,59.05 JP6.3
  Bottom 0.254: JTAG.1 29.43,71.75 37.3,63.88 47.21,63.88 48.73,62.35 JP6.3
TMS
  Bottom 0.254: JTAG.5 24.6,70.48 24.6,67.81 30.31,62.1 37.81,62.1 38.82,61.08 JP8.3
VCC
  TOP 0.61: JP2.2 5.55,62.35 6.18,62.99 41.11,62.99 | 41.11,62.99 53.17,62.99 54.57,61.59 56.22,61.59 56.25,61.56 R10.2 59.12,61.56 59.14,61.59 59.2,61.54 R11.2 59.27,60.45 60.9,58.82 J5.1 | 41.11,62.99 JP3.2
VCC430
  TOP 0.254: R4.1 7.63,56.69 7.46,56.51 JP2.1
  TOP 0.61: JP2.1 5.55,52.06 8.47,49.14 8.47,47.87 8.42,47.82 R2.2 8.34,48.89 1.49,48.89 1.49,28.57 J1.7 8.98,28.57 15.35,28.6 C5.1 16.22,32.37 16.22,33.83 | 16.22,33.83 16.22,33.9 | 16.22,33.83 C6.+
  Bottom 0.61: J1.7 6.69,28.57 16.29,25.42 17.51,25.34 17.57,25.34 U1.7
  pour vcc430: 0.47,0.63 76.67,0.63 76.67,74.29 0.47,74.29
XIN  (via drill 0.8)
  TOP 0.254: v16.22,18.41 Q1.2 | v16.22,18.41 15.71,18.92 12.92,18.92 12.89,18.94 C2.1 | v16.22,18.41 17.49,18.41 18.76,17.14 24.35,17.14 27.39,20.19 27.39,24.25 27.9,24.76 28.41,24.76 28.49,24.84 U1.8
  TOP 0.406: 12.66,18.94 12.66,18.92 | 12.66,18.94 C2.1 | R7.2 12.66,19.05 12.66,18.94
XOUT  (via drill 0.8)
  TOP 0.254: 16.22,14.6 v16.22,13.33 15.46,12.57 C1.1 | 16.22,14.6 Q1.1 | U1.9 32.06,24.34 32.73,23.74 32.73,20.95 29.68,17.9 26.63,17.9 23.33,14.6 16.22,14.6
  TOP 0.406: R5.2 12.54,12.44 C1.1
XTLGND  (via drill 0.7)
  other vias: 14.19,15.87
  pour TOP: 18,20.95 9.74,20.95 9.61,11.04 11.65,11.04 18,11.3

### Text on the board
tPlace: Dim: 78 x 75mm | MSP-TS430PM64A | Rev.: 1.1
tNames: Vcc | int | ext | <- JTAG | <- SBW | RoHS | 60 | 55 | 45 | 5 | 40 | 10 | 35 | 20 | 25 | 30
tDocu: Open JP1 if LCD is connected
